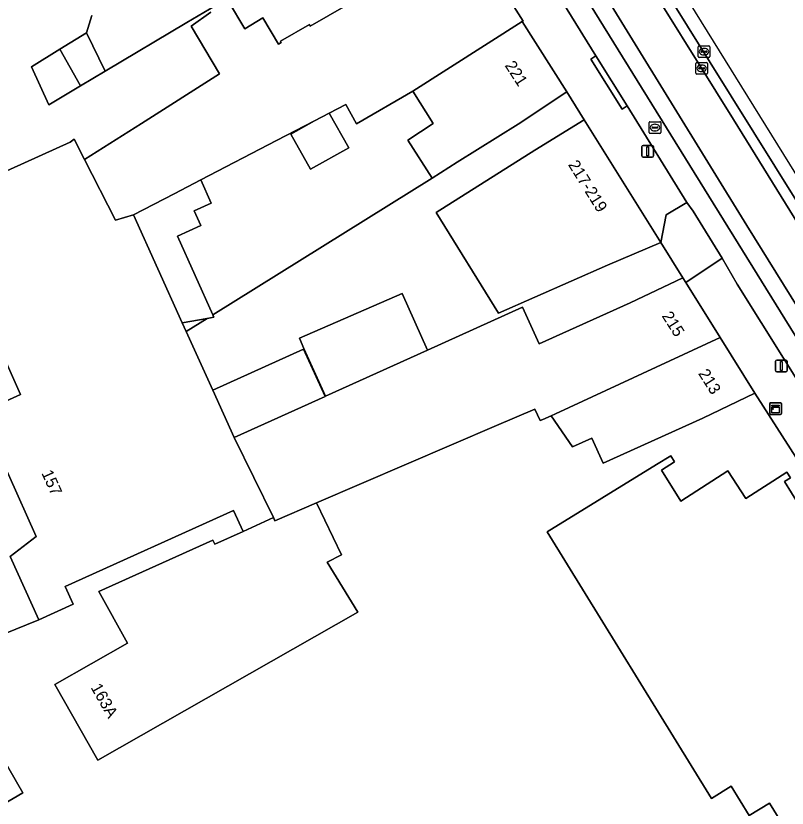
# Model space of a CAD drawing. Extents: x 159888 to 160761, y 384031 to 384750.
# Drawn here: x 160503.3 to 160569.1, y 384372.4 to 384440 of the extents above; entities that cross this region are included whole.
import ezdxf

# ---------------------------------------------------------------- set-up
doc = ezdxf.new("R2010")
doc.units = 0
for name, color, linetype in [('IMGEO_Berm_open', 7, 'Continuous'), ('IMGEO_Erf', 7, 'Continuous'), ('IMGEO_Kast', 7, 'Continuous'), ('IMGEO_Kolk', 7, 'Continuous'), ('IMGEO_Lichtmast', 7, 'Continuous'), ('IMGEO_Pand', 7, 'Continuous'), ('IMGEO_Pand_nummerreeks', 7, 'Continuous'), ('IMGEO_Parkeervlak_gesloten', 7, 'Continuous'), ('IMGEO_Parkeervlak_open', 7, 'Continuous'), ('IMGEO_Rijbaan_lokaal_gesloten', 7, 'Continuous'), ('IMGEO_Rijbaan_lokaal_open', 7, 'Continuous'), ('IMGEO_Rioolput', 7, 'Continuous'), ('IMGEO_Voetpad_open', 7, 'Continuous')]:
    doc.layers.add(name, color=color, linetype=linetype)

msp = doc.modelspace()

# ---------------------------------------------------------------- linework, layer by layer
at = {"layer": 'IMGEO_Berm_open'}
msp.add_lwpolyline([(160573.734, 384418.106), (160547.482, 384460.166), (160546.333, 384462.102), (160545.604, 384461.675), (160546.003, 384460.9), (160546.729, 384459.74), (160564.541, 384431.158), (160615.861, 384348.269), (160631.369, 384323.299), (160632.074, 384323.722), (160631.044, 384325.378)], close=True, dxfattribs=at)
at = {"layer": 'IMGEO_Erf'}
for points in [[(160521.263, 384441.462), (160517.869, 384439.44), (160510.896, 384435.287), (160508.802, 384434.04), (160506.072, 384432.414), (160504.603, 384435.668), (160507.038, 384437.163), (160509.314, 384438.56), (160509.757, 384440.031)], [(160496.507, 384424.091), (160507.911, 384429.24), (160508.248, 384429.476), (160509.129, 384427.751), (160513.984, 384430.831), (160520.667, 384435.072), (160518.227, 384439.122), (160519.911, 384440.336)], [(160570.55, 384401.238), (160566.359, 384407.814), (160561.92, 384405.677), (160553.405, 384401.832), (160552.434, 384403.983), (160550.785, 384403.239), (160548.964, 384405.87), (160548.249, 384405.567), (160548.024, 384405.465), (160547.579, 384406.451), (160544.293, 384405.04), (160528.944, 384398.447), (160531.06, 384394.011), (160529.854, 384393.381), (160532.476, 384389.133), (160510.261, 384376.495), (160506.59, 384382.948), (160512.814, 384386.489), (160510.357, 384390.876), (160520.089, 384395.264), (160520.242, 384394.924), (160522.66, 384396.015), (160521.851, 384397.809), (160507.479, 384391.32), (160508.168, 384389.793), (160505.218, 384388.461), (160494.187, 384384.008)], [(160569.536, 384369.697), (160567.598, 384372.839), (160565.878, 384371.778), (160564.339, 384374.273), (160562.643, 384373.227), (160548.621, 384395.966), (160557.952, 384401.72), (160559.167, 384402.469), (160559.495, 384401.938), (160558.386, 384401.254), (160560.02, 384398.606), (160564.059, 384401.198), (160565.583, 384398.823), (160569.095, 384401.076), (160569.403, 384400.593), (160568.891, 384400.267), (160570.083, 384398.332)], [(160500.691, 384379.183), (160503.875, 384373.713), (160498.413, 384370.534)]]:
    msp.add_lwpolyline(points, dxfattribs=at)
for points in [[(160526.742, 384429.913), (160528.774, 384431.061), (160525.511, 384429.366), (160519.049, 384426.008), (160519.945, 384424.022), (160518.484, 384423.363), (160519.051, 384422.106), (160517.063, 384421.208), (160520.093, 384414.495), (160538.821, 384426.153), (160536.731, 384429.407), (160538.883, 384430.814), (160537.148, 384433.59), (160532.337, 384430.788), (160531.427, 384432.44), (160530.025, 384431.712), (160531.695, 384428.759), (160528.435, 384426.917)], [(160519.614, 384414.196), (160517.476, 384413.822), (160517.815, 384413.072)]]:
    msp.add_lwpolyline(points, close=True, dxfattribs=at)
at = {"layer": 'IMGEO_Kast'}
for p, q in [((160567.62, 384406.075), (160567.62, 384406.916)), ((160567.62, 384406.916), (160567.62, 384406.075)), ((160567.695, 384407), (160568.536, 384407)), ((160568.536, 384407), (160567.695, 384407)), ((160568.62, 384406.925), (160568.62, 384406.084)), ((160568.62, 384406.084), (160568.62, 384406.925)), ((160568.545, 384406), (160567.704, 384406)), ((160567.704, 384406), (160568.545, 384406))]:
    msp.add_line(p, q, dxfattribs=at)
for points in [[(160567.815, 384406.79), (160568.415, 384406.79), (160568.415, 384406.705), (160567.815, 384406.705), (160567.815, 384406.79)], [(160567.815, 384406.615), (160568.415, 384406.615), (160568.415, 384406.126), (160567.815, 384406.126), (160567.815, 384406.615)]]:
    msp.add_lwpolyline(points, dxfattribs=at)
msp.add_circle((160567.899, 384406.464), 0.0377, dxfattribs=at)
for centre, start, end in [((160567.698, 384406.922), 92.4484, 184.28452), ((160567.698, 384406.922), 92.4484, 184.28452), ((160568.542, 384406.922), 2.4484, 94.28452), ((160568.542, 384406.922), 2.4484, 94.28452), ((160567.698, 384406.078), 182.4484, 274.28452), ((160567.698, 384406.078), 182.4484, 274.28452), ((160568.542, 384406.078), 272.4484, 4.28452), ((160568.542, 384406.078), 272.4484, 4.28452)]:
    msp.add_arc(centre, 0.0779, start, end, dxfattribs=at)
at = {"layer": 'IMGEO_Kolk'}
for p, q in [((160561.511, 384436.527), (160561.511, 384437.379)), ((160561.586, 384437.453), (160562.438, 384437.453)), ((160561.999, 384437.233), (160562.024, 384437.233)), ((160562.512, 384437.379), (160562.512, 384436.527)), ((160562.438, 384436.453), (160561.586, 384436.453)), ((160561.77, 384436.947), (160561.77, 384436.959)), ((160562.208, 384436.91), (160561.81, 384436.91)), ((160561.813, 384436.996), (160562.211, 384436.996)), ((160562.022, 384436.673), (160561.997, 384436.673)), ((160562.254, 384436.959), (160562.254, 384436.947)), ((160561.312, 384435.104), (160561.312, 384435.956)), ((160561.387, 384436.03), (160562.239, 384436.03)), ((160561.8, 384435.81), (160561.825, 384435.81)), ((160562.313, 384435.956), (160562.313, 384435.104)), ((160561.571, 384435.524), (160561.571, 384435.536)), ((160562.009, 384435.487), (160561.611, 384435.487)), ((160561.614, 384435.573), (160562.012, 384435.573)), ((160561.823, 384435.25), (160561.798, 384435.25)), ((160562.055, 384435.536), (160562.055, 384435.524)), ((160562.239, 384435.03), (160561.387, 384435.03))]:
    msp.add_line(p, q, dxfattribs=at)
for points in [[(160561.511, 384436.527), (160561.511, 384437.379)], [(160561.586, 384437.453), (160562.438, 384437.453)], [(160562.512, 384437.379), (160562.512, 384436.527)], [(160562.438, 384436.453), (160561.586, 384436.453)], [(160561.312, 384435.104), (160561.312, 384435.956)], [(160561.387, 384436.03), (160562.239, 384436.03)], [(160562.313, 384435.956), (160562.313, 384435.104)], [(160562.239, 384435.03), (160561.387, 384435.03)]]:
    msp.add_lwpolyline(points, dxfattribs=at)
for centre, radius, start, end in [((160561.588, 384437.377), 0.0765, 91.55205, 178.44795), ((160561.588, 384437.377), 0.0765, 91.55205, 178.44795), ((160562.436, 384437.377), 0.0765, 1.55205, 88.44795), ((160562.436, 384437.377), 0.0765, 1.55205, 88.44795), ((160561.588, 384436.529), 0.0765, 181.55205, 268.44795), ((160561.588, 384436.529), 0.0765, 181.55205, 268.44795), ((160561.81, 384436.956), 0.0403, 85.87752, 175.75265), ((160561.807, 384436.946), 0.0366, 178.93798, 274.71019), ((160562.211, 384436.953), 0.043, 264.86636, 352.45326), ((160562.215, 384436.958), 0.0386, 1.73085, 96.63898), ((160562.436, 384436.529), 0.0765, 271.55205, 358.44795), ((160562.436, 384436.529), 0.0765, 271.55205, 358.44795), ((160561.389, 384435.954), 0.0765, 91.55205, 178.44795), ((160561.389, 384435.954), 0.0765, 91.55205, 178.44795), ((160562.237, 384435.954), 0.0765, 1.55205, 88.44795), ((160562.237, 384435.954), 0.0765, 1.55205, 88.44795), ((160561.389, 384435.106), 0.0765, 181.55205, 268.44795), ((160561.389, 384435.106), 0.0765, 181.55205, 268.44795), ((160561.611, 384435.533), 0.0403, 85.87752, 175.75265), ((160561.608, 384435.523), 0.0366, 178.93798, 274.71019), ((160562.012, 384435.53), 0.043, 264.86636, 352.45326), ((160562.016, 384435.535), 0.0386, 1.73085, 96.63898), ((160562.237, 384435.106), 0.0765, 271.55205, 358.44795), ((160562.237, 384435.106), 0.0765, 271.55205, 358.44795)]:
    msp.add_arc(centre, radius, start, end, dxfattribs=at)
for centre, major_axis, ratio, start_param, end_param in [((160561.998, 384436.953), (-0.387, 0.002), 0.722429, 4.712389, 7.853982), ((160562.023, 384436.953), (-0.39, 0.002), 0.717154, 1.570796, 4.712389), ((160561.799, 384435.53), (-0.387, 0.002), 0.722429, 4.712389, 7.853982), ((160561.824, 384435.53), (-0.39, 0.002), 0.717154, 1.570796, 4.712389)]:
    msp.add_ellipse(centre, major_axis=major_axis, ratio=ratio, start_param=start_param, end_param=end_param, dxfattribs=at)
at = {"layer": 'IMGEO_Lichtmast'}
for p, q in [((160556.709, 384428.051), (160556.709, 384428.851)), ((160556.709, 384428.851), (160556.709, 384428.051)), ((160556.809, 384428.951), (160557.599, 384428.951)), ((160557.599, 384428.951), (160556.809, 384428.951)), ((160557.699, 384428.851), (160557.699, 384428.051)), ((160557.699, 384428.051), (160557.699, 384428.851)), ((160557.599, 384427.951), (160556.809, 384427.951)), ((160556.809, 384427.951), (160557.599, 384427.951)), ((160568.118, 384409.734), (160568.118, 384410.534)), ((160568.118, 384410.534), (160568.118, 384409.734)), ((160568.218, 384410.634), (160569.008, 384410.634)), ((160569.008, 384410.634), (160568.218, 384410.634)), ((160569.108, 384410.534), (160569.108, 384409.734)), ((160569.108, 384409.734), (160569.108, 384410.534)), ((160569.008, 384409.634), (160568.218, 384409.634)), ((160568.218, 384409.634), (160569.008, 384409.634))]:
    msp.add_line(p, q, dxfattribs=at)
for points in [[(160557.129, 384428.826), (160557.279, 384428.826), (160557.279, 384428.076), (160557.129, 384428.076), (160557.129, 384428.826)], [(160568.538, 384410.509), (160568.688, 384410.509), (160568.688, 384409.759), (160568.538, 384409.759), (160568.538, 384410.509)]]:
    msp.add_lwpolyline(points, dxfattribs=at)
for centre, start, end in [((160556.809, 384428.851), 90, 180), ((160556.809, 384428.851), 90, 180), ((160557.599, 384428.851), 0, 90), ((160557.599, 384428.851), 360, 90), ((160556.809, 384428.051), 180, 270), ((160556.809, 384428.051), 180, 270), ((160557.599, 384428.051), 270, 0), ((160557.599, 384428.051), 270, 0), ((160568.218, 384410.534), 90, 180), ((160568.218, 384410.534), 90, 180), ((160569.008, 384410.534), 0, 90), ((160569.008, 384410.534), 360, 90), ((160568.218, 384409.734), 180, 270), ((160568.218, 384409.734), 180, 270), ((160569.008, 384409.734), 270, 0), ((160569.008, 384409.734), 270, 0)]:
    msp.add_arc(centre, 0.1, start, end, dxfattribs=at)
at = {"layer": 'IMGEO_Pand'}
for points in [[(160519.911, 384440.336), (160518.227, 384439.122), (160520.667, 384435.072), (160513.984, 384430.831), (160509.129, 384427.751), (160511.769, 384422.587), (160513.319, 384423.031), (160516.785, 384424.832), (160519.049, 384426.008), (160525.511, 384429.366), (160528.774, 384431.061), (160530.025, 384431.712), (160531.427, 384432.44), (160532.337, 384430.788), (160537.148, 384433.59), (160546.499, 384439.524), (160546.57, 384439.568), (160542.745, 384445.624)], [(160509.757, 384440.031), (160509.314, 384438.56), (160510.896, 384435.287), (160517.869, 384439.44), (160521.263, 384441.462)], [(160521.409, 384441.221), (160522.814, 384438.904), (160524.349, 384439.834), (160525.702, 384437.6), (160525.907, 384437.724), (160525.85, 384437.852), (160528.331, 384439.264), (160528.396, 384439.12), (160533.01, 384441.804)], [(160533.01, 384441.804), (160528.396, 384439.12), (160528.331, 384439.264), (160525.85, 384437.852), (160525.907, 384437.724), (160525.702, 384437.6), (160524.349, 384439.834), (160522.814, 384438.904), (160521.409, 384441.221)], [(160501.513, 384412.497), (160503.674, 384407.711), (160500.243, 384406.162), (160505.018, 384395.587), (160502.777, 384393.869), (160505.218, 384388.461), (160508.168, 384389.793), (160507.479, 384391.32), (160521.851, 384397.809), (160522.66, 384396.015), (160525.259, 384397.188), (160521.9, 384404.024), (160520.076, 384408.063), (160517.815, 384413.072), (160517.476, 384413.822), (160513.319, 384423.031), (160511.769, 384422.587), (160509.129, 384427.751), (160508.248, 384429.476), (160507.911, 384429.24), (160496.507, 384424.091)], [(160570.083, 384398.332), (160568.891, 384400.267), (160569.403, 384400.593), (160569.095, 384401.076), (160565.583, 384398.823), (160564.059, 384401.198), (160560.02, 384398.606), (160558.386, 384401.254), (160559.495, 384401.938), (160559.167, 384402.469), (160557.952, 384401.72), (160548.621, 384395.966), (160562.643, 384373.227), (160564.339, 384374.273), (160565.878, 384371.778), (160567.598, 384372.839), (160569.536, 384369.697)]]:
    msp.add_lwpolyline(points, dxfattribs=at)
for points in [[(160550.312, 384433.524), (160546.499, 384439.524), (160537.148, 384433.59), (160538.883, 384430.814), (160536.731, 384429.407), (160538.821, 384426.153), (160540.943, 384427.519), (160546.154, 384430.774)], [(160508.802, 384434.04), (160510.896, 384435.287), (160509.314, 384438.56), (160507.038, 384437.163)], [(160508.802, 384434.04), (160507.038, 384437.163), (160504.603, 384435.668), (160506.072, 384432.414)], [(160530.025, 384431.712), (160528.774, 384431.061), (160526.742, 384429.913), (160528.435, 384426.917), (160531.695, 384428.759)], [(160551.79, 384431.149), (160547.57, 384428.561), (160539.149, 384423.216), (160544.483, 384414.641), (160553.765, 384418.731), (160558.33, 384420.679)], [(160519.049, 384426.008), (160516.785, 384424.832), (160513.319, 384423.031), (160517.476, 384413.822), (160519.614, 384414.196), (160519.889, 384414.244), (160520.183, 384414.296), (160520.093, 384414.495), (160517.063, 384421.208), (160519.051, 384422.106), (160518.484, 384423.363), (160519.945, 384424.022)], [(160563.392, 384412.563), (160560.463, 384417.251), (160560.216, 384417.647), (160555.702, 384415.512), (160547.94, 384412.007), (160546.525, 384415.141), (160538.422, 384411.483), (160529.703, 384407.547), (160529.662, 384407.528), (160521.9, 384404.024), (160525.259, 384397.188), (160525.388, 384396.92), (160528.944, 384398.447), (160544.293, 384405.04), (160547.579, 384406.451), (160548.024, 384405.465), (160548.249, 384405.567), (160548.964, 384405.87), (160549.329, 384406.035)], [(160566.359, 384407.814), (160563.392, 384412.563), (160549.329, 384406.035), (160548.964, 384405.87), (160550.785, 384403.239), (160552.434, 384403.983), (160553.405, 384401.832), (160561.92, 384405.677)], [(160520.076, 384408.063), (160521.9, 384404.024), (160529.662, 384407.528), (160527.838, 384411.567)], [(160528.944, 384398.447), (160525.388, 384396.92), (160525.259, 384397.188), (160522.66, 384396.015), (160520.242, 384394.924), (160520.089, 384395.264), (160510.357, 384390.876), (160512.814, 384386.489), (160506.59, 384382.948), (160510.261, 384376.495), (160532.476, 384389.133), (160529.854, 384393.381), (160531.06, 384394.011)], [(160503.875, 384373.713), (160500.691, 384379.183), (160496.065, 384376.531), (160490.663, 384373.365), (160484.01, 384369.637), (160486.241, 384365.833), (160486.707, 384366.106), (160487.774, 384364.286), (160491.959, 384366.777), (160493.098, 384367.44), (160498.413, 384370.534)]]:
    msp.add_lwpolyline(points, close=True, dxfattribs=at)
at = {"layer": 'IMGEO_Parkeervlak_gesloten'}
for points in [[(160591.404, 384377.897), (160543.713, 384454.868), (160537.603, 384464.743), (160537.564, 384464.718)], [(160537.553, 384461.036), (160540.083, 384456.992), (160542.538, 384453.014), (160544.582, 384449.757), (160546.017, 384447.47), (160547.886, 384444.522), (160552.792, 384436.596), (160555.44, 384432.318), (160560.546, 384424.068), (160561.084, 384423.337), (160563.566, 384419.321), (160564.854, 384417.108), (160570.857, 384407.526), (160585.252, 384384.362), (160600.12, 384360.1), (160613.675, 384338.3), (160614.145, 384337.587), (160615.758, 384338.612), (160591.404, 384377.897)]]:
    msp.add_lwpolyline(points, dxfattribs=at)
at = {"layer": 'IMGEO_Parkeervlak_open'}
msp.add_lwpolyline([(160527.867, 384411.614), (160529.703, 384407.547), (160538.422, 384411.483), (160536.245, 384416.303), (160527.477, 384412.518)], close=True, dxfattribs=at)
at = {"layer": 'IMGEO_Rijbaan_lokaal_gesloten'}
for points in [[(160530.872, 384485.299), (160529.392, 384487.663), (160528.599, 384488.928), (160527.089, 384491.477), (160521.986, 384499.927), (160522.875, 384494.017), (160521.397, 384493.999), (160525.927, 384486.643), (160525.936, 384486.628), (160565.675, 384422.118), (160628.254, 384321.427), (160631.369, 384323.299), (160615.861, 384348.269), (160564.541, 384431.158), (160546.729, 384459.74), (160546.003, 384460.9), (160545.604, 384461.675)], [(160633.021, 384324.291), (160626.323, 384335.141), (160581.707, 384407.406), (160547.381, 384462.76), (160546.333, 384462.102), (160547.482, 384460.166), (160573.734, 384418.106), (160631.044, 384325.378), (160632.074, 384323.722), (160633.021, 384324.291)]]:
    msp.add_lwpolyline(points, dxfattribs=at)
msp.add_lwpolyline([(160525.936, 384486.628), (160525.927, 384486.643), (160521.397, 384493.999), (160519.494, 384493.976), (160523.701, 384487.143), (160524.133, 384486.422), (160537.603, 384464.743), (160543.713, 384454.868), (160591.404, 384377.897), (160615.758, 384338.612), (160624.721, 384324.154), (160626.898, 384320.642), (160628.254, 384321.427), (160565.675, 384422.118)], close=True, dxfattribs=at)
at = {"layer": 'IMGEO_Rijbaan_lokaal_open'}
msp.add_lwpolyline([(160539.149, 384423.216), (160547.57, 384428.561), (160551.79, 384431.149), (160550.312, 384433.524), (160546.154, 384430.774), (160540.943, 384427.519), (160538.821, 384426.153), (160520.093, 384414.495), (160520.183, 384414.296), (160519.889, 384414.244), (160519.614, 384414.196), (160517.815, 384413.072), (160520.076, 384408.063), (160527.838, 384411.567), (160529.662, 384407.528), (160529.703, 384407.547), (160527.867, 384411.614), (160527.477, 384412.518), (160536.245, 384416.303), (160538.422, 384411.483), (160546.525, 384415.141), (160547.94, 384412.007), (160555.702, 384415.512), (160560.216, 384417.647), (160558.33, 384420.679), (160553.765, 384418.731), (160544.483, 384414.641)], close=True, dxfattribs=at)
msp.add_lwpolyline([(160494.187, 384384.008), (160505.218, 384388.461), (160502.777, 384393.869), (160505.018, 384395.587), (160500.243, 384406.162), (160503.674, 384407.711), (160501.513, 384412.497)], dxfattribs=at)
at = {"layer": 'IMGEO_Rioolput'}
for p, q in [((160557.327, 384430.051), (160557.327, 384430.903)), ((160557.402, 384430.977), (160558.254, 384430.977)), ((160557.586, 384430.471), (160557.586, 384430.483)), ((160558.024, 384430.434), (160557.626, 384430.434)), ((160557.629, 384430.52), (160558.027, 384430.52)), ((160557.815, 384430.757), (160557.84, 384430.757)), ((160558.07, 384430.483), (160558.07, 384430.471)), ((160558.328, 384430.903), (160558.328, 384430.051)), ((160558.254, 384429.977), (160557.402, 384429.977)), ((160557.838, 384430.197), (160557.813, 384430.197))]:
    msp.add_line(p, q, dxfattribs=at)
for points in [[(160557.327, 384430.051), (160557.327, 384430.903)], [(160557.402, 384430.977), (160558.254, 384430.977)], [(160558.328, 384430.903), (160558.328, 384430.051)], [(160558.254, 384429.977), (160557.402, 384429.977)]]:
    msp.add_lwpolyline(points, dxfattribs=at)
for centre, radius, start, end in [((160557.404, 384430.901), 0.0765, 91.55205, 178.44795), ((160557.404, 384430.901), 0.0765, 91.55205, 178.44795), ((160557.626, 384430.48), 0.0403, 85.87752, 175.75265), ((160557.623, 384430.47), 0.0366, 178.93798, 274.71019), ((160558.027, 384430.477), 0.043, 264.86636, 352.45326), ((160558.031, 384430.482), 0.0386, 1.73085, 96.63898), ((160558.252, 384430.901), 0.0765, 1.55205, 88.44795), ((160558.252, 384430.901), 0.0765, 1.55205, 88.44795), ((160557.404, 384430.053), 0.0765, 181.55205, 268.44795), ((160557.404, 384430.053), 0.0765, 181.55205, 268.44795), ((160558.252, 384430.053), 0.0765, 271.55205, 358.44795), ((160558.252, 384430.053), 0.0765, 271.55205, 358.44795)]:
    msp.add_arc(centre, radius, start, end, dxfattribs=at)
for centre, major_axis, ratio, start_param, end_param in [((160557.814, 384430.477), (-0.387, 0.002), 0.722429, 4.712389, 7.853982), ((160557.839, 384430.477), (-0.39, 0.002), 0.717154, 1.570796, 4.712389)]:
    msp.add_ellipse(centre, major_axis=major_axis, ratio=ratio, start_param=start_param, end_param=end_param, dxfattribs=at)
at = {"layer": 'IMGEO_Voetpad_open'}
for points in [[(160542.745, 384445.624), (160546.57, 384439.568), (160546.499, 384439.524), (160550.312, 384433.524), (160551.79, 384431.149), (160558.33, 384420.679), (160558.781, 384423.024), (160560.546, 384424.068), (160555.44, 384432.318), (160555.022, 384432.056), (160552.355, 384436.322), (160552.792, 384436.596), (160547.886, 384444.522)], [(160570.857, 384407.526), (160564.854, 384417.108), (160563.566, 384419.321), (160560.463, 384417.251), (160563.392, 384412.563), (160566.359, 384407.814), (160570.55, 384401.238)]]:
    msp.add_lwpolyline(points, dxfattribs=at)
for points in [[(160552.792, 384436.596), (160552.355, 384436.322), (160555.022, 384432.056), (160555.44, 384432.318)], [(160561.084, 384423.337), (160560.546, 384424.068), (160558.781, 384423.024), (160558.33, 384420.679), (160560.216, 384417.647), (160560.463, 384417.251), (160563.566, 384419.321)]]:
    msp.add_lwpolyline(points, close=True, dxfattribs=at)

# ---------------------------------------------------------------- texts
at = {"layer": 'IMGEO_Pand_nummerreeks'}
for s, rotation, p in [('221', 302.84746, (160544.971, 384435.776)), ('217-219', 301.9651, (160550.378, 384427.309)), ('215', 302.30888, (160558.378, 384414.408)), ('213', 302.29742, (160561.487, 384409.491)), ('157', 294.33904, (160505.432, 384400.997)), ('163A', 299.63317, (160509.631, 384382.699))]:
    msp.add_text(s, height=1, rotation=rotation, dxfattribs=at).set_placement(p)

doc.saveas('drawing.dxf')
